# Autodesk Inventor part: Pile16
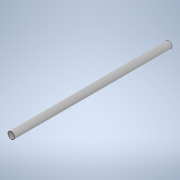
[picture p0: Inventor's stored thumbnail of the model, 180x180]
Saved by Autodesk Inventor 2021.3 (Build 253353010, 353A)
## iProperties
Created: 2021-11
Part Number: Pile16
Material: Steel, Mild
Document SubType Name: Modeling
Designer: u1426
Density: 7.85 g/cm^3
Appearance: Smooth - Medium Gray
Author: u1426
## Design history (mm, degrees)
sketch "Sketch1"
  geometry: C1 r 203.2 at (0, 0); C2 r 190.5 at (0, 0); 1 further point
  constraints: 2 centre point, 2 coincident
  dimensions: "d0" = 406.4 diameter of C1; "d1" = 12.7 radial gap between concentric circles of C2 C1
extrude "Extrusion1" new body sketch "Sketch1" distance "d2" = 9144; taper "d3" = 0 deg
body "Solid1"
